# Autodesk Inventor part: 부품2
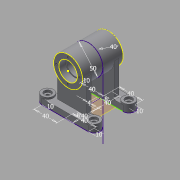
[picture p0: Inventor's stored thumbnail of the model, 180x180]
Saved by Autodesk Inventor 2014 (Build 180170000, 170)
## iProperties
Created: 2015-11
Part Number: 부품2
Material: 일반
Document SubType Name: Modeling
Designer: Owner
Density: 1 g/cm^3
Appearance: 기본값
Author: Owner
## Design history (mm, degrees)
sketch "스케치1"
  geometry: C1 r 25 at (0, 0); 1 further point
  constraints: 1 centre point, 1 coincident
  dimensions: "d1" = 50 diameter of C1
extrude "돌출1" new body sketch "스케치1" stored distance "d2" = 70; taper "d3" = 0 deg
sketch "스케치2"
  geometry: C1 r 25 at (0, 0) reference; C2 r 16 at (0, 0)
  constraints: 1 centre point, 1 coincident
  dimensions: "d4" = 32 diameter of C2
extrude "돌출2" cut sketch "스케치2" distance "d5" = 12; taper "d6" = 0 deg
sketch "스케치3"
  geometry: C1 r 25 at (0, 0) reference; C2 r 16 at (0, 0)
  constraints: 1 centre point, 1 coincident
  dimensions: "d7" = 32 diameter of C2
extrude "돌출3" cut sketch "스케치3" distance "d8" = 12; taper "d9" = 0 deg
sketch "스케치4"
  geometry: C1 r 16 at (0, 0) reference; C2 r 14 at (0, 0)
  constraints: 1 centre point, 1 coincident
  dimensions: "d10" = 28 diameter of C2
extrude "돌출4" cut sketch "스케치4" stored distance "d11" = 12; taper "d12" = 0 deg
node "작업 평면1"
sketch "스케치6"
  geometry: L1 (0, 0)-(0, 40); L2 (0, 0)-(0, -40); L3 (0, 40)-(-40, 40); L4 (-40, 40)-(0, 40); L5 (0, 40)-(40, 40); L6 (0, -40)-(-40, -40); L7 (0, -40)-(40, -40); L8 (-40, 40)-(-40, 30); L9 (-40, -40)-(-40, -30); L10 (40, -40)-(40, -30); L11 (40, 40)-(40, 30); L12 (-40, 20)-(40, 20); L13 (-40, -20)-(40, -20); L14 (0, -20)-(4, -20); L15 (0, 20)-(0, 28); L16 (0, -20)-(0, -28); A1 r 10 centre (-40, 30) between (-40, 40) and (-40, 20); A2 r 10 centre (-40, -30) between (-40, -40) and (-40, -20); A3 r 10 centre (40, -30) between (40, -40) and (40, -20); A4 r 10 centre (40, 30) between (40, 40) and (40, 20)
  constraints: 32 end point, 8 equal length, 8 point on circle, 4 centre point, 4 coincident, 3 point on line, 2 midpoint, 2 perpendicular, 2 tangent, 1 vertical
  dimensions: "d14" = 40 distance of L1.start L1.end; "d15" = 40 distance of L1.start L2.end; "d16" = 40 distance of L1.end L3.end; "d17" = 40 distance of L1.end L5.end; "d18" = 40 distance of L2.end L6.end; "d19" = 40 distance of L2.end L7.end; "d20" = 10 distance of L3.end L8.end; "d21" = 10 distance of L6.end L9.end; "d24" = 10 distance of L7.end L10.end; "d25" = 10 distance of L5.end L11.end; "d27" = 4 distance of L14.start L14.end; "d32" = 8 distance of L15.start L15.end; "d33" = 8 distance of L14.start L16.end
extrude "돌출5" join sketch "스케치6" distance "d28" = 13; taper "d29" = 0 deg
extrude "돌출6" join sketch "스케치6" distance "d30" = 10; taper "d31" = 0 deg
sketch "스케치7"
  geometry: C1 r 16 at (0, 0) reference; C2 r 25 at (0, 0) reference
sketch "스케치8"
  geometry: L1 (0, -25)-(108.525, -25); L2 (0, 25)-(113.838, 25); C1 r 16 at (0, 0) reference; A1 r 25 centre (0, 0) between (0, -25) and (0, 25) reference; 1 further point
  constraints: 4 end point, 2 point on circle, 2 tangent, 1 horizontal, 1 parallel
  node "투영된 루프1"
sketch "스케치10"
  geometry: 1 further point
sketch "스케치11"
  geometry: L1 (-3.559, 0)-(-28.559, 0); L2 (0, 20)-(0, 28); L3 (0, 28)-(-25, 28); L4 (-25, 28)-(-25, 20); L5 (0, 28)-(25, 28); L6 (25, 28)-(25, 20); L7 (25, 20)-(-25, 20); L8 (0, -20)-(0, -28); L9 (0, -28)-(-25, -28); L10 (0, -28)-(25, -28); L11 (25, -28)-(25, -20); L12 (25, -20)-(-25, -20); L13 (-25, -20)-(-25, -28); 1 further point
  constraints: 26 end point, 7 perpendicular, 4 parallel, 1 collinear, 1 horizontal
  dimensions: "d34" = 25 distance of L1.start L1.end; "d35" = 8 distance of L2.start L2.end; "d36" = 25 distance of L2.end L3.end; "d37" = 25 distance of L2.end L5.end; "d38" = 8 distance of L8.start L8.end; "d39" = 25 distance of L8.end L9.end; "d40" = 25 distance of L8.end L10.end
extrude "돌출7" join sketch "스케치11" stored distance "d41" = 10; taper "d42" = 0 deg
sketch "스케치12"
  geometry: C1 r 25 at (0, 0) reference; A1 r 20 centre (0, 0) between (0, 20) and (-20, 0); 2 further points
  constraints: 4 point on circle, 1 centre point, 1 coincident
  dimensions: "d43" = 40 diameter of A1
hole "구멍1" sketch "스케치12" diameter "d44" = 3.242; stored, may be unused: countersink angle "d48" = 90 deg, drill point angle "d50" = 118 deg; dims "d45" = 8, "d46" = 19.05, "d47" = 4.775, "d49" = 10
hole "구멍2" sketch "스케치12" diameter "d51" = 3.242; stored, may be unused: countersink angle "d55" = 90 deg, drill point angle "d57" = 118 deg; dims "d52" = 8, "d53" = 19.05, "d54" = 4.775, "d56" = 10
sketch "스케치13"
  geometry: C1 r 25 at (0, 0) reference; A1 r 20 centre (0, 0) between (0, 20) and (-20, 0); 2 further points
  constraints: 4 point on circle, 1 centre point, 1 coincident
  dimensions: "d58" = 40 diameter of A1
hole "구멍3" sketch "스케치13" at (0, 20), (-20, 0), (0, -20), (20, 0) diameter "d59" = 3.242; stored, may be unused: countersink angle "d63" = 90 deg, drill point angle "d65" = 118 deg; dims "d60" = 8, "d61" = 19.05, "d62" = 4.775, "d64" = 10
sketch "스케치14"
  geometry: C1 r 10 at (0, 0) reference; C2 r 6 at (0, 0); C3 r 10 at (-60, 0) reference; C4 r 10 at (-60, -80) reference; C5 r 10 at (0, -80) reference; C6 r 6 at (0, -80); C7 r 6 at (-60, -80); C8 r 6 at (-60, 0); 1 further point
  constraints: 4 centre point, 4 coincident
  dimensions: "d66" = 12 diameter of C2; "d67" = 12 diameter of C6; "d68" = 12 diameter of C7; "d69" = 12 diameter of C8
extrude "돌출8" cut sketch "스케치14" distance "d70" = 4; taper "d71" = 0 deg
sketch "스케치15"
  geometry: C1 r 10 at (0, 0) reference; C2 r 6 at (0, 0); 1 further point
  constraints: 1 centre point, 1 coincident
  dimensions: "d72" = 12 diameter of C2
extrude "돌출9" cut sketch "스케치15" distance "d73" = 4; taper "d74" = 0 deg
sketch "스케치16"
  geometry: C1 r 10 at (0, 0) reference; C2 r 6 at (0, 0); 1 further point
  constraints: 1 centre point, 1 coincident
  dimensions: "d75" = 12 diameter of C2
extrude "돌출10" cut sketch "스케치16" distance "d76" = 4; taper "d77" = 0 deg
sketch "스케치17"
  geometry: C1 r 10 at (0, 0) reference; C2 r 6 at (0, 0); 1 further point
  constraints: 1 centre point, 1 coincident
  dimensions: "d78" = 12 diameter of C2
extrude "돌출11" cut sketch "스케치17" distance "d79" = 4; taper "d80" = 0 deg
sketch "스케치18"
  geometry: C1 r 6 at (0, 0) reference; C2 r 3 at (0, 0); 1 further point
  constraints: 1 centre point, 1 coincident
  dimensions: "d81" = 6 diameter of C2
extrude "돌출12" cut sketch "스케치18" stored distance "d82" = 4; taper "d83" = 0 deg
sketch "스케치19"
  geometry: C1 r 6 at (0, 0) reference; C2 r 3 at (0, 0); C3 r 10 at (0, -80) reference; C4 r 10 at (-60, -80) reference; C5 r 3 at (-60, -80); C6 r 3 at (0, -80); 1 further point
  constraints: 3 centre point, 3 coincident
  dimensions: "d84" = 6 diameter of C2; "d85" = 6 diameter of C5
extrude "돌출13" cut sketch "스케치19" stored distance "d86" = 4; taper "d87" = 0 deg
node "솔리드1"
other parameters: "d13" = 68
